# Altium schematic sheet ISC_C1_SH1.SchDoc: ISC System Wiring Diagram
size B; DrawnBy: Filiberto Clara; Engineer: Filiberto Clara; Organization: LIGO Laboratory; Address1: California Institute of Technology; Address2: Massachusetts Institute of Technology; SheetNumber: 1; SheetTotal: 39
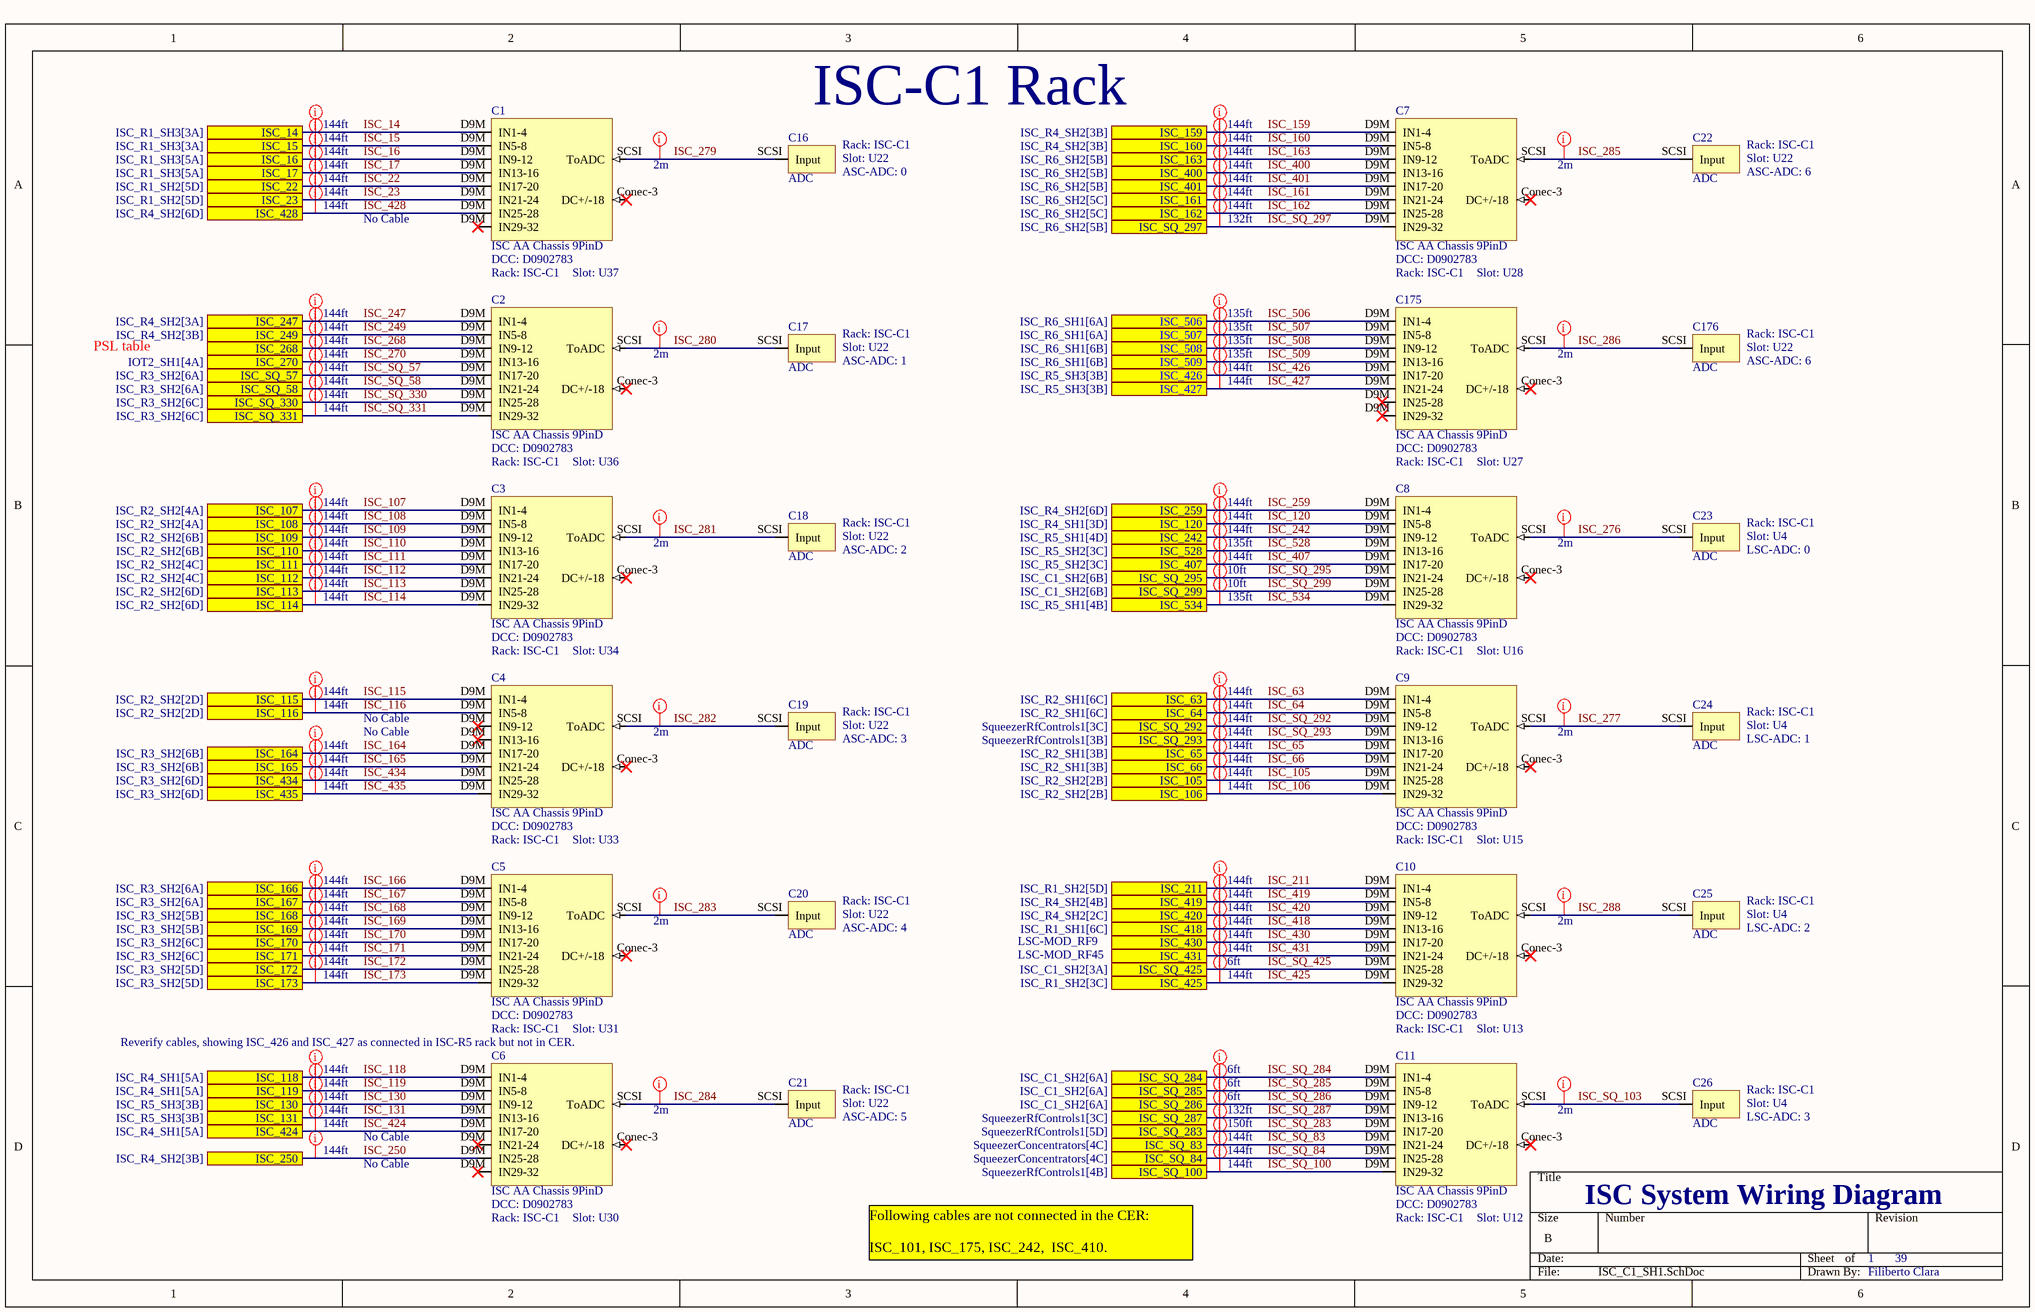
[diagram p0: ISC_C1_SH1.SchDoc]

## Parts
C1  ISC AA Chassis 9PinD  DCC: D0902783  Rack: ISC-C1  Slot: U37
C2  ISC AA Chassis 9PinD  DCC: D0902783  Rack: ISC-C1  Slot: U36
C3  ISC AA Chassis 9PinD  DCC: D0902783  Rack: ISC-C1  Slot: U34
C4  ISC AA Chassis 9PinD  DCC: D0902783  Rack: ISC-C1  Slot: U33
C5  ISC AA Chassis 9PinD  DCC: D0902783  Rack: ISC-C1  Slot: U31
C6  ISC AA Chassis 9PinD  DCC: D0902783  Rack: ISC-C1  Slot: U30
C7  ISC AA Chassis 9PinD  DCC: D0902783  Rack: ISC-C1  Slot: U28
C8  ISC AA Chassis 9PinD  DCC: D0902783  Rack: ISC-C1  Slot: U16
C9  ISC AA Chassis 9PinD  DCC: D0902783  Rack: ISC-C1  Slot: U15
C10  ISC AA Chassis 9PinD  DCC: D0902783  Rack: ISC-C1  Slot: U13
C11  ISC AA Chassis 9PinD  DCC: D0902783  Rack: ISC-C1  Slot: U12
C16  ADC  Rack: ISC-C1  Slot: U22  ASC-ADC: 0
C17  ADC  Rack: ISC-C1  Slot: U22  ASC-ADC: 1
C18  ADC  Rack: ISC-C1  Slot: U22  ASC-ADC: 2
C19  ADC  Rack: ISC-C1  Slot: U22  ASC-ADC: 3
C20  ADC  Rack: ISC-C1  Slot: U22  ASC-ADC: 4
C21  ADC  Rack: ISC-C1  Slot: U22  ASC-ADC: 5
C22  ADC  Rack: ISC-C1  Slot: U22  ASC-ADC: 6
C23  ADC  Rack: ISC-C1  Slot: U4  LSC-ADC: 0
C24  ADC  Rack: ISC-C1  Slot: U4  LSC-ADC: 1
C25  ADC  Rack: ISC-C1  Slot: U4  LSC-ADC: 2
C26  ADC  Rack: ISC-C1  Slot: U4  LSC-ADC: 3
C175  ISC AA Chassis 9PinD  DCC: D0902783  Rack: ISC-C1  Slot: U27
C176  ADC  Rack: ISC-C1  Slot: U22  ASC-ADC: 6

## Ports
ISC_14 (see ISC_R1_SH3[3A]), ISC_15 (see ISC_R1_SH3[3A]), ISC_16 (see ISC_R1_SH3[5A]), ISC_17 (see ISC_R1_SH3[5A]), ISC_22 (see ISC_R1_SH2[5D]), ISC_23 (see ISC_R1_SH2[5D]), ISC_63 (see ISC_R2_SH1[6C]), ISC_64 (see ISC_R2_SH1[6C]), ISC_65 (see ISC_R2_SH1[3B]), ISC_66 (see ISC_R2_SH1[3B]), ISC_105 (see ISC_R2_SH2[2B]), ISC_106 (see ISC_R2_SH2[2B]), ISC_107 (see ISC_R2_SH2[4A]), ISC_108 (see ISC_R2_SH2[4A]), ISC_109 (see ISC_R2_SH2[6B]), ISC_110 (see ISC_R2_SH2[6B]), ISC_111 (see ISC_R2_SH2[4C]), ISC_112 (see ISC_R2_SH2[4C]), ISC_113 (see ISC_R2_SH2[6D]), ISC_114 (see ISC_R2_SH2[6D]), ISC_115 (see ISC_R2_SH2[2D]), ISC_116 (see ISC_R2_SH2[2D]), ISC_118 (see ISC_R4_SH1[5A]), ISC_119 (see ISC_R4_SH1[5A]), ISC_120 (see ISC_R4_SH1[3D]), ISC_130 (see ISC_R5_SH3[3B]), ISC_131 (see ISC_R5_SH3[3B]), ISC_159 (see ISC_R4_SH2[3B]), ISC_160 (see ISC_R4_SH2[3B]), ISC_161 (see ISC_R6_SH2[5C]), ISC_162 (see ISC_R6_SH2[5C]), ISC_163 (see ISC_R6_SH2[5B]), ISC_164 (see ISC_R3_SH2[6B]), ISC_165 (see ISC_R3_SH2[6B]), ISC_166 (see ISC_R3_SH2[6A]), ISC_167 (see ISC_R3_SH2[6A]), ISC_168 (see ISC_R3_SH2[5B]), ISC_169 (see ISC_R3_SH2[5B]), ISC_170 (see ISC_R3_SH2[6C]), ISC_171 (see ISC_R3_SH2[6C]), ISC_172 (see ISC_R3_SH2[5D]), ISC_173 (see ISC_R3_SH2[5D]), ISC_211 (see ISC_R1_SH2[5D]), ISC_242 (see ISC_R5_SH1[4D]), ISC_247 (see ISC_R4_SH2[3A]), ISC_249 (see ISC_R4_SH2[3B]), ISC_250 (see ISC_R4_SH2[3B]), ISC_259 (see ISC_R4_SH2[6D]), ISC_268, ISC_270 (see IOT2_SH1[4A]), ISC_400 (see ISC_R6_SH2[5B]), ISC_401 (see ISC_R6_SH2[5B]), ISC_407 (see ISC_R5_SH2[3C]), ISC_418 (see ISC_R1_SH1[6C]), ISC_419 (see ISC_R4_SH2[4B]), ISC_420 (see ISC_R4_SH2[2C]), ISC_424 (see ISC_R4_SH1[5A]), ISC_425 (see ISC_R1_SH2[3C]), ISC_426 (see ISC_R5_SH3[3B]), ISC_427 (see ISC_R5_SH3[3B]), ISC_428 (see ISC_R4_SH2[6D]), ISC_430, ISC_431, ISC_434 (see ISC_R3_SH2[6D]), ISC_435 (see ISC_R3_SH2[6D]), ISC_506 (see ISC_R6_SH1[6A]), ISC_507 (see ISC_R6_SH1[6A]), ISC_508 (see ISC_R6_SH1[6B]), ISC_509 (see ISC_R6_SH1[6B]), ISC_528 (see ISC_R5_SH2[3C]), ISC_534 (see ISC_R5_SH1[4B]), ISC_SQ_57 (see ISC_R3_SH2[6A]), ISC_SQ_58 (see ISC_R3_SH2[6A]), ISC_SQ_83 (see SqueezerConcentrators[4C]), ISC_SQ_84 (see SqueezerConcentrators[4C]), ISC_SQ_100 (see SqueezerRfControls1[4B]), ISC_SQ_283 (see SqueezerRfControls1[5D]), ISC_SQ_284 (see ISC_C1_SH2[6A]), ISC_SQ_285 (see ISC_C1_SH2[6A]), ISC_SQ_286 (see ISC_C1_SH2[6A]), ISC_SQ_287 (see SqueezerRfControls1[3C]), ISC_SQ_292 (see SqueezerRfControls1[3C]), ISC_SQ_293 (see SqueezerRfControls1[3B]), ISC_SQ_295 (see ISC_C1_SH2[6B]), ISC_SQ_297 (see ISC_R6_SH2[5B]), ISC_SQ_299 (see ISC_C1_SH2[6B]), ISC_SQ_330 (see ISC_R3_SH2[6C]), ISC_SQ_331 (see ISC_R3_SH2[6C]), ISC_SQ_425 (see ISC_C1_SH2[3A])

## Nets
ISC_14: C1.D9M(IN1-4) ; port ISC_14
ISC_15: C1.D9M(IN5-8) ; port ISC_15
ISC_16: C1.D9M(IN9-12) ; port ISC_16
ISC_17: C1.D9M(IN13-16) ; port ISC_17
ISC_22: C1.D9M(IN17-20) ; port ISC_22
ISC_23: C1.D9M(IN21-24) ; port ISC_23
ISC_63: C9.D9M(IN1-4) ; port ISC_63
ISC_64: C9.D9M(IN5-8) ; port ISC_64
ISC_65: C9.D9M(IN17-20) ; port ISC_65
ISC_66: C9.D9M(IN21-24) ; port ISC_66
ISC_105: C9.D9M(IN25-28) ; port ISC_105
ISC_106: C9.D9M(IN29-32) ; port ISC_106
ISC_107: C3.D9M(IN1-4) ; port ISC_107
ISC_108: C3.D9M(IN5-8) ; port ISC_108
ISC_109: C3.D9M(IN9-12) ; port ISC_109
ISC_110: C3.D9M(IN13-16) ; port ISC_110
ISC_111: C3.D9M(IN17-20) ; port ISC_111
ISC_112: C3.D9M(IN21-24) ; port ISC_112
ISC_113: C3.D9M(IN25-28) ; port ISC_113
ISC_114: C3.D9M(IN29-32) ; port ISC_114
ISC_115: C4.D9M(IN1-4) ; port ISC_115
ISC_116: C4.D9M(IN5-8) ; port ISC_116
ISC_118: C6.D9M(IN1-4) ; port ISC_118
ISC_119: C6.D9M(IN5-8) ; port ISC_119
ISC_120: C8.D9M(IN5-8) ; port ISC_120
ISC_130: C6.D9M(IN9-12) ; port ISC_130
ISC_131: C6.D9M(IN13-16) ; port ISC_131
ISC_159: C7.D9M(IN1-4) ; port ISC_159
ISC_160: C7.D9M(IN5-8) ; port ISC_160
ISC_161: C7.D9M(IN21-24) ; port ISC_161
ISC_162: C7.D9M(IN25-28) ; port ISC_162
ISC_163: C7.D9M(IN9-12) ; port ISC_163
ISC_164: C4.D9M(IN17-20) ; port ISC_164
ISC_165: C4.D9M(IN21-24) ; port ISC_165
ISC_166: C5.D9M(IN1-4) ; port ISC_166
ISC_167: C5.D9M(IN5-8) ; port ISC_167
ISC_168: C5.D9M(IN9-12) ; port ISC_168
ISC_169: C5.D9M(IN13-16) ; port ISC_169
ISC_170: C5.D9M(IN17-20) ; port ISC_170
ISC_171: C5.D9M(IN21-24) ; port ISC_171
ISC_172: C5.D9M(IN25-28) ; port ISC_172
ISC_173: C5.D9M(IN29-32) ; port ISC_173
ISC_211: C10.D9M(IN1-4) ; port ISC_211
ISC_242: C8.D9M(IN9-12) ; port ISC_242
ISC_247: C2.D9M(IN1-4) ; port ISC_247
ISC_249: C2.D9M(IN5-8) ; port ISC_249
ISC_250: C6.D9M(IN25-28) ; port ISC_250
ISC_259: C8.D9M(IN1-4) ; port ISC_259
ISC_268: C2.D9M(IN9-12) ; port ISC_268
ISC_270: C2.D9M(IN13-16) ; port ISC_270
ISC_276: C8.SCSI(ToADC) C23.SCSI(Input)
ISC_277: C9.SCSI(ToADC) C24.SCSI(Input)
ISC_279: C1.SCSI(ToADC) C16.SCSI(Input)
ISC_280: C2.SCSI(ToADC) C17.SCSI(Input)
ISC_281: C3.SCSI(ToADC) C18.SCSI(Input)
ISC_282: C4.SCSI(ToADC) C19.SCSI(Input)
ISC_283: C5.SCSI(ToADC) C20.SCSI(Input)
ISC_284: C6.SCSI(ToADC) C21.SCSI(Input)
ISC_285: C7.SCSI(ToADC) C22.SCSI(Input)
ISC_286: C175.SCSI(ToADC) C176.SCSI(Input)
ISC_288: C10.SCSI(ToADC) C25.SCSI(Input)
ISC_400: C7.D9M(IN13-16) ; port ISC_400
ISC_401: C7.D9M(IN17-20) ; port ISC_401
ISC_407: C8.D9M(IN17-20) ; port ISC_407
ISC_418: C10.D9M(IN13-16) ; port ISC_418
ISC_419: C10.D9M(IN5-8) ; port ISC_419
ISC_420: C10.D9M(IN9-12) ; port ISC_420
ISC_424: C6.D9M(IN17-20) ; port ISC_424
ISC_425: C10.D9M(IN29-32) ; port ISC_425
ISC_426: C175.D9M(IN17-20) ; port ISC_426
ISC_427: C175.D9M(IN21-24) ; port ISC_427
ISC_428: C1.D9M(IN25-28) ; port ISC_428
ISC_430: C10.D9M(IN17-20) ; port ISC_430
ISC_431: C10.D9M(IN21-24) ; port ISC_431
ISC_434: C4.D9M(IN25-28) ; port ISC_434
ISC_435: C4.D9M(IN29-32) ; port ISC_435
ISC_506: C175.D9M(IN1-4) ; port ISC_506
ISC_507: C175.D9M(IN5-8) ; port ISC_507
ISC_508: C175.D9M(IN9-12) ; port ISC_508
ISC_509: C175.D9M(IN13-16) ; port ISC_509
ISC_528: C8.D9M(IN13-16) ; port ISC_528
ISC_534: C8.D9M(IN29-32) ; port ISC_534
ISC_SQ_57: C2.D9M(IN17-20) ; port ISC_SQ_57
ISC_SQ_58: C2.D9M(IN21-24) ; port ISC_SQ_58
ISC_SQ_83: C11.D9M(IN21-24) ; port ISC_SQ_83
ISC_SQ_84: C11.D9M(IN25-28) ; port ISC_SQ_84
ISC_SQ_100: C11.D9M(IN29-32) ; port ISC_SQ_100
ISC_SQ_103: C11.SCSI(ToADC) C26.SCSI(Input)
ISC_SQ_283: C11.D9M(IN17-20) ; port ISC_SQ_283
ISC_SQ_284: C11.D9M(IN1-4) ; port ISC_SQ_284
ISC_SQ_285: C11.D9M(IN5-8) ; port ISC_SQ_285
ISC_SQ_286: C11.D9M(IN9-12) ; port ISC_SQ_286
ISC_SQ_287: C11.D9M(IN13-16) ; port ISC_SQ_287
ISC_SQ_292: C9.D9M(IN9-12) ; port ISC_SQ_292
ISC_SQ_293: C9.D9M(IN13-16) ; port ISC_SQ_293
ISC_SQ_295: C8.D9M(IN21-24) ; port ISC_SQ_295
ISC_SQ_297: C7.D9M(IN29-32) ; port ISC_SQ_297
ISC_SQ_299: C8.D9M(IN25-28) ; port ISC_SQ_299
ISC_SQ_330: C2.D9M(IN25-28) ; port ISC_SQ_330
ISC_SQ_331: C2.D9M(IN29-32) ; port ISC_SQ_331
ISC_SQ_425: C10.D9M(IN25-28) ; port ISC_SQ_425

Not connected (* = marked no-connect by the designer): C1 Conec-3(DC+/-18)*; C2 Conec-3(DC+/-18)*; C3 Conec-3(DC+/-18)*; C4 Conec-3(DC+/-18)*; C5 Conec-3(DC+/-18)*; C6 Conec-3(DC+/-18)*; C7 Conec-3(DC+/-18)*; C8 Conec-3(DC+/-18)*; C9 Conec-3(DC+/-18)*; C10 Conec-3(DC+/-18)*; C11 Conec-3(DC+/-18)*; C175 Conec-3(DC+/-18)*

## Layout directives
Length: 2m: ISC_276, ISC_277, ISC_279, ISC_280, ISC_281, ISC_282, ISC_283, ISC_284, ISC_285, ISC_286, ISC_288, ISC_SQ_103
Length: 144ft: ISC_14, ISC_15, ISC_16, ISC_17, ISC_22, ISC_23, ISC_63, ISC_64, ISC_65, ISC_66, ISC_105, ISC_106, ISC_107, ISC_108, ISC_109, ISC_110, ISC_111, ISC_112, ISC_113, ISC_114, ISC_115, ISC_116, ISC_118, ISC_119, ISC_120, ISC_130, ISC_131, ISC_159, ISC_160, ISC_161, ISC_162, ISC_163, ISC_164, ISC_165, ISC_166, ISC_167, ISC_168, ISC_169, ISC_170, ISC_171, ISC_172, ISC_173, ISC_211, ISC_242, ISC_247, ISC_249, ISC_250, ISC_259, ISC_268, ISC_270, ISC_400, ISC_401, ISC_407, ISC_418, ISC_419, ISC_420, ISC_424, ISC_425, ISC_426, ISC_427, ISC_428, ISC_430, ISC_431, ISC_434, ISC_435, ISC_SQ_57, ISC_SQ_58, ISC_SQ_83, ISC_SQ_84, ISC_SQ_100, ISC_SQ_292, ISC_SQ_293, ISC_SQ_330, ISC_SQ_331
Length: 10ft: ISC_SQ_295, ISC_SQ_299
Length: 132ft: ISC_SQ_287, ISC_SQ_297
Length: 6ft: ISC_SQ_284, ISC_SQ_285, ISC_SQ_286, ISC_SQ_425
Length: 150ft: ISC_SQ_283
Length: 135ft: ISC_506, ISC_507, ISC_508, ISC_509, ISC_528, ISC_534

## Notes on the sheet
- (near C16) ISC-C1 Rack
- No Cable
- PSL table
- LSC-MOD_RF9
- LSC-MOD_RF45
- (near C6) Reverify cables, showing ISC_426 and ISC_427 as connected in ISC-R5 rack but not in CER.
- Following cables are not connected in the CER:
  ISC_101, ISC_175, ISC_242,  ISC_410.

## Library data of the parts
C1-C11 C175 = AA_9pinAll: Serial: Sxxxxxxx
C16-C26 C176 = ADC-16: 16 Bit ADC; Serial: Sxxxxxxx; System: ISC; DCC: tbd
